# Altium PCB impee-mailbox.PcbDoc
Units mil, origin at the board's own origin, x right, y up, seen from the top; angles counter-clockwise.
Board outline 4040 x 2300 mil, 2 copper layers (Top Layer, Bottom Layer), stack 64.8 mil thick; 81 components, 52 nets, 267 pads, 176 vias.
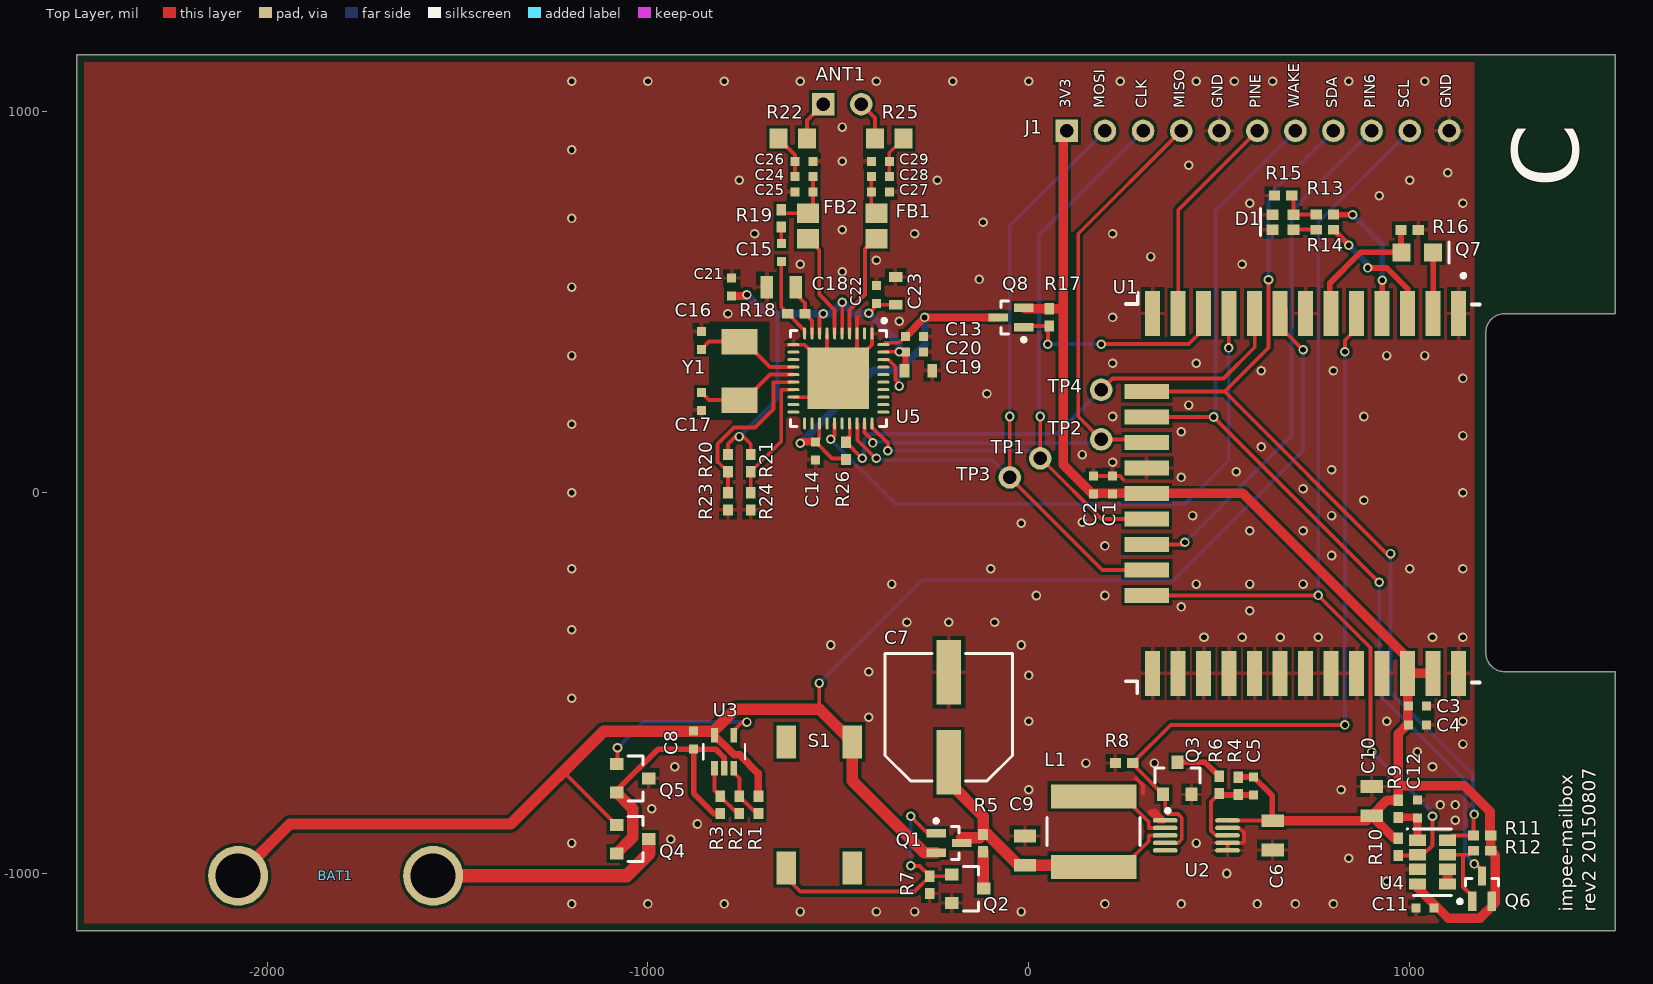
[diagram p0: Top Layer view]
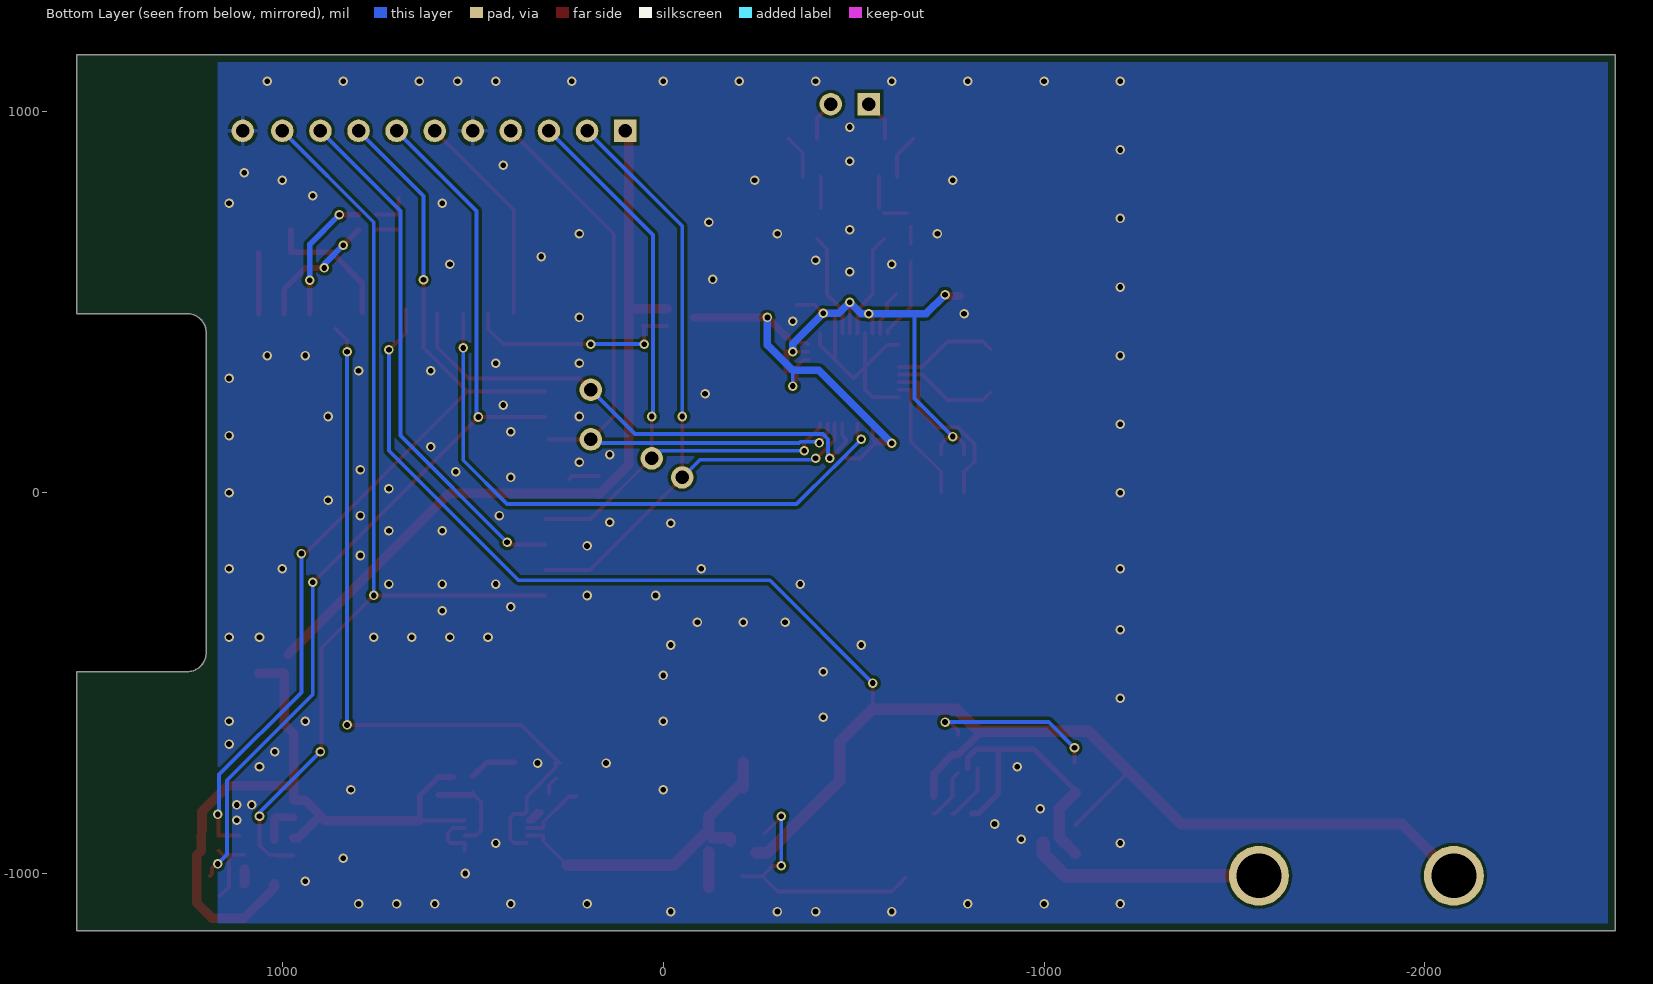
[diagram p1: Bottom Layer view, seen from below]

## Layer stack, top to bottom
Top Solder: solder mask 0.4, Solder Resist, Dk 3.5
Top Layer: signal copper 1.4
Dielectric1: core 62, FR-4, Dk 4.8
Bottom Layer: signal copper 1.4
Bottom Solder: solder mask 0.4, Solder Resist, Dk 3.5

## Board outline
-2500,-1150 -2500,1150 1540,1150 1540,470 1250,470 ccw(c1250,420) 1200,420 1200,-419.9 ccw(c1250,-420) 1250,-470 1540,-470 1540,-1150

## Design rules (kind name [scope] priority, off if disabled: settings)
Clearance "I2C clearance" [(InNet('SCL') AND IsTrack) vs (InNet('SDA') AND IsTrack)] p1: gap=8
Clearance "NPTH Clearance" [IsThruPin and (not PadIsPlated)] p2: gap=10
Clearance "Diff to Poly" [(InDifferentialPairClass('All Differential Pairs')) OR InNet('PinA') OR InNet('PinB') vs InPolygon] p3: gap=30
Clearance "50_OHM to Poly" [InNetClass('50_OHM') and (IsTrack or IsArc) vs InPolygon] p4: gap=30
Clearance "Polygon to All" [InPolygon] p5: gap=8
Clearance [All] p6: gap=6
Clearance "Pad Clearance" [IsPad vs IsPad] p7: gap=8
Clearance "XTAL Clearance" [(InNet('OSC32_IN') OR InNet('OSC32_OUT') OR InComponent('Y1')) vs InPolygon] p8: gap=30
HoleSize [All] p1: absolutevalues=TRUE maxlimit=125 minlimit=1 maxpercent=80.000 minpercent=20.000
HoleToHoleClearance [All] p1: gap=6 allowstackedmicrovias=TRUE
MinimumSolderMaskSliver [All] p1: minsoldermaskwidth=1
PolygonConnect "Direct GND" [InNet('GND') and IsVia] p1: connectstyle=Direct reliefconductorwidth=10 reliefentries=4 polygonreliefangle="90 Angle" airgapwidth=10
PolygonConnect [All] p2: connectstyle=Relief reliefconductorwidth=10 reliefentries=4 polygonreliefangle="90 Angle" airgapwidth=10
RoutingVias [All] p1: holewidth=15 width=25 viastyle="Through Hole" minholewidth=15 minwidth=25 maxholewidth=15 maxwidth=25
SilkToSilkClearance [All] p1: silktosilkclearance=3.94
SilkToSolderMaskClearance [IsPad vs Not HasFootprint('IMP_MODULE')] p1: minsilkscreentomaskgap=7.87 clearancetoexposedcopper=TRUE
SolderMaskExpansion [All] p1: expansion=4
Width 50_OHM [InNetClass('50_OHM')] p1: maxlimit=8.96 minlimit=8.96 preferedwidth=8.96 impedancedriven=TRUE minimp=50.000000 maximp=50.000000 favimp=50.000000
Width [All] p2: maxlimit=100 minlimit=6 preferedwidth=10 minimp=50.000000 maximp=50.000000 favimp=50.000000 checkconnectedcopper=TRUE
25 further rules are at their usual default settings.

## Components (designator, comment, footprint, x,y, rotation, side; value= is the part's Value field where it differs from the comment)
ANT1 "Header" HDR254P1X2-N -540,1020 r0 top
BAT1 "BATTERY" 12BH321P-GR -1820,0 r270 top locked
C1 "Ceramic Capacitor" CAPC1005X07N 220,20 r270 top
C2 "Ceramic Capacitor" CAPC1005X07N 170,20 r270 top
C3 "Ceramic Capacitor" CAPC1005X07N 1020,-560 r180 top
C4 "Ceramic Capacitor" CAPC1005X07N 1020,-610 r180 top
C5 "Ceramic Capacitor" CAPC1005X07N 590,-770 r90 top
C6 "Ceramic Capacitor" CAPC2012X14N 640,-900 r90 top
C7 "Polarized Capacitor" CAPAE8983X55N -210,-590 r90 top
C8 "Ceramic Capacitor" CAPC1005X07N -880,-650 r90 top
C9 "Ceramic Capacitor" CAPC2012X14N -10,-940 r270 top
C10 "Ceramic Capacitor" CAPC2012X14N 900,-810 r270 top
C11 "Ceramic Capacitor" CAPC1005X07N 1040,-1090 r0 top
C12 "Ceramic Capacitor" CAPC1005X07N 1020,-830 r270 top
C13 "Ceramic Capacitor" CAPC1005X07N -300,410 r180 top
C14 "Ceramic Capacitor" CAPC1005X07N -560,110 r90 top
C15 "Ceramic Capacitor" CAPC1005X07N -650,630 r90 top
C16 "Ceramic Capacitor" CAPC1005X07N -860,400 r270 top
C17 "Ceramic Capacitor" CAPC1005X07N -860,240 r90 top
C18 "Ceramic Capacitor" CAPC2012X14N -650,540 r0 top
C19 "Ceramic Capacitor" CAPC1608X10N -290,320 r180 top
C20 "Ceramic Capacitor" CAPC1005X07N -300,370 r180 top
C21 "Ceramic Capacitor" CAPC1005X07N -780,540 r270 top
C22 "Ceramic Capacitor" CAPC1005X07N -400,520 r270 top
C23 "Ceramic Capacitor" CAPC1608X10N -350,530 r270 top
C24 "Ceramic Capacitor" CAPC1005X07N -590,830 r180 top
C25 "Ceramic Capacitor" CAPC1005X07N -590,790 r0 top
C26 "Ceramic Capacitor" CAPC1005X07N -590,870 r180 top
C27 "Ceramic Capacitor" CAPC1005X07N -390,790 r0 top
C28 "Ceramic Capacitor" CAPC1005X07N -390,830 r0 top
C29 "Ceramic Capacitor" CAPC1005X07N -390,870 r180 top
D1 "LED Red and Green" LED1616X07N-REDGREEN 667.56,710.31 r0 top
FB1 "Ferrite Bead" INDC2012X11N -400,700 r90 top
FB2 "Ferrite Bead" INDC2012X11N -580,700 r90 top
J1 "Header" HDR254P1X11-N 100,950 r0 top
L1 "Inductor" INDP6060X28N 170,-890 r90 top
Q1 "PFET" SOT65P210X110-3N -210,-920 r0 top
Q2 "N-Channel MOSFET" SOT95P300X130-3N -160,-1040 r0 top
Q3 "N-Channel MOSFET" SOT95P300X130-3N 390,-750 r90 top
Q4 "N-Channel MOSFET" SOT95P300X130-3N -1040,-910 r0 top
Q5 "N-Channel MOSFET" SOT95P300X130-3N -1040,-750 r0 top
Q6 "PFET" SOT65P210X110-3N 1190,-1040 r90 top
Q7 "PHOTOTRANSISTOR" PHOTOTRANS2012X13 1020,630 r180 top
Q8 "PFET" SOT65P210X110-3N -46.54,460 r180 top
R1 "Resistor" RESC1005X04N -710,-820 r270 top
R2 "Resistor" RESC1005X04N -760,-820 r270 top
R3 "Resistor" RESC1005X04N -810,-820 r270 top
R4 "Resistor" RESC1005X04N 550,-770 r270 top
R5 "Resistor" RESC1005X04N -120,-920 r270 top
R6 "Resistor" RESC1005X04N 500,-767.36 r90 top
R7 "Resistor" RESC1005X04N -260,-1030 r270 top
R8 "Resistor" RESC1005X04N 250,-710 r180 top
R9 "Resistor" RESC1005X04N 970,-830 r90 top
R10 "Resistor" RESC1005X04N 970,-930 r270 top
R11 "Resistor" RESC1005X04N 1190,-900 r180 top
R12 "Resistor" RESC1005X04N 1190,-940 r180 top
R13 "Resistor" RESC1005X04N 777.56,730.31 r180 top
R14 "Resistor" RESC1005X04N 777.56,690.31 r180 top
R15 "Resistor" RESC1005X04N 667.56,780.31 r0 top
R16 "Resistor" RESC1005X04N 1000,690 r0 top
R17 "Resistor" RESC1005X04N 53.46,460 r270 top
R18 "Resistor" RESC1005X04N -610,470 r0 top
R19 "Resistor" RESC1005X04N -650,720 r90 top
R20 "Resistor" RESC1005X04N -790,77.36 r270 top
R21 "Resistor" RESC1005X04N -730,77.36 r270 top
R22 "Resistor" RESC2012X07N -620,930 r0 top
R23 "Resistor" RESC1005X04N -790,-22.64 r270 top
R24 "Resistor" RESC1005X04N -730,-22.64 r270 top
R25 "Resistor" RESC2012X07N -366.38,930 r180 top
R26 "Resistor" RESC1005X04N -480,110 r90 top
S1 "Push Button" BTN600X600X430-4N -550,-820 r0 top
TP1 "Testpoint" TP254P1X1-TH 30,90 r0 top
TP2 "Testpoint" TP254P1X1-TH 190,140 r90 top
TP3 "Testpoint" TP254P1X1-TH -50,40 r90 top
TP4 "Testpoint" TP254P1X1-TH 190,270 r90 top
U1 "imp module" IMP_MODULE 290,490 r270 top locked
U2 "XC9128" MSOP50P490X116-10N 440,-900 r0 top
U3 "MIC841" SOT65P200X125-5N -800,-680 r90 top
U4 "TMD2772" SON97P240X155-8N 1060,-970 r0 top
U5 "PN532" QFN50P600X600X100_HS-41N -500,300 r270 top
Y1 "XTAL" XTAL5032X135 -760,320 r270 top

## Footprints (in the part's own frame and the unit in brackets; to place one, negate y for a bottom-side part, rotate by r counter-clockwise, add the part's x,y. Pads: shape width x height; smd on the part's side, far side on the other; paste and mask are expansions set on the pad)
12BH321P-GR [mm] "2xAA Series Battery Clip with Through-Hole PCB Mount"
  round 4 hole 3: +(25.55,-6.5) -(25.55,6.5)
  body extent -28.45,-16.51 28.45,16.51, height 16.11
BTN600X600X430-4N [mm] "Push Button 4-Terminal"
  rect 1.3x2.2 smd: 1(-2.2,4.2) 2(-2.2,-4.2) 3(2.2,-4.2) 4(2.2,4.2)
  body extent -3,-5 3,5, height 5.07
CAPAE8983X55N [mm] "Aluminum Electrolytic Capacitor, Body 8.30x8.30x5.50mm, IPC Medium Density"
  rect 4.3x1.65 smd: 1(-3,0) 2(3,0)
  silkscreen extent -4.25,-4.25 4.25,4.25, body extent -4.45,-4.15 4.45,4.15, height 6.2
CAPC1005X07N [mm] "Chip Capacitor, 2-Leads, Body 1.0x0.5mm, IPC Medium Density"
  rect 0.6x0.6 smd: 1(-0.6,0) 2(0.6,0)
  body extent -0.5,-0.25 0.5,0.25, height 0.6
CAPC1608X10N [mm] "Chip Capacitor, 2-Leads, Body 1.6x0.8mm, IPC Medium Density"
  rect 0.65x0.9 smd: 1(-0.925,0) 2(0.925,0)
  body extent -0.8,-0.4 0.8,0.4, height 0.95
CAPC2012X14N [mm] "Chip Capacitor, 2-Leads, Body 2.0x1.3mm, IPC Medium Density"
  rect 0.85x1.5 smd: 1(-0.975,0) 2(0.975,0)
  body extent -1,-0.6 1,0.6, height 1.4
HDR254P1X2-N [mm] "HDR, 2.54mm Pitch, 2-Pin"
  rect 1.5x1.5 hole 0.9: 1(0,0)
  round 1.5 hole 0.9: 2(2.54,0)
  body extent -1.27,-1.27 3.81,1.27, height 8.54
HDR254P1X11-N [mm] "HDR, 2.54mm Pitch, 11-Pin"
  rect 1.5x1.5 hole 0.9: 1(0,0)
  round 1.5 hole 0.9: 2(2.54,0) 3(5.08,0) 4(7.62,0) 5(10.16,0) 6(12.7,0) 7(15.24,0) 8(17.78,0) 9(20.32,0) 10(22.86,0) 11(25.5,0)
  body extent -1.27,-1.28 26.85,1.28, height 8.54
IMP_MODULE [mm] "Imp Module, Shadow and Chase"
  rect 3x1 smd: 1(0.5,21.3) 2(0.5,19.6) 3(0.5,17.9) 4(0.5,16.2) 5(0.5,14.5) 6(0.5,12.8) 7(0.5,11.1) 8(0.5,9.4) 9(0.5,7.7) 10(0.5,6) 11(0.5,4.3) 12(0.5,2.6) 13(0.5,0.9) 23(24.5,0.9) 24(24.5,2.6) 25(24.5,4.3) 26(24.5,6) 27(24.5,7.7) 28(24.5,9.4) 29(24.5,11.1) 30(24.5,12.8) 31(24.5,14.5) 32(24.5,16.2) 33(24.5,17.9) 34(24.5,19.6) 35(24.5,21.3)
  rect 1x3 smd: 14(5.7,0.5) 15(7.4,0.5) 16(9.1,0.5) 17(10.8,0.5) 18(12.5,0.5) 19(14.2,0.5) 20(15.9,0.5) 21(17.6,0.5) 22(19.3,0.5)
  silkscreen extent -2.15,-0.89 25.81,22.7, body extent 0,0 25,31, height 1.7
INDC2012X11N [mm] "Chip Inductor, 2-Leads, Body 2.0x1.3mm, IPC Medium Density"
  rect 1.3x1.45 smd: 1(-0.85,0) 2(0.85,0)
  body extent -1.1,-0.72 1.1,0.72, height 1.1
INDP6060X28N [mm] "Precision Wire Wound Inductor, 2-Leads, Body 6.0x6.0mm, IPC Medium Density"
  rect 1.6x5.7 smd: 1(-2.35,0) 2(2.35,0)
  silkscreen extent -0.92,-3.1 0.92,3.1, body extent -3.1,-3.1 3.1,3.1, height 2.8
LED1616X07N-REDGREEN [mm] "Bi-Color LED, 0606 (1616 metric), Red, Green"
  rect 0.8x0.7 smd: AG(0.7,-0.5) AR(0.7,0.5) KG(-0.7,-0.5) KR(-0.7,0.5)
  silkscreen extent -1.5,-0.9 -1.5,0.9, body extent -0.8,-0.8 0.8,0.8, height 0.7
MSOP50P490X116-10N [mm] "MSOP, 10-Leads, Body 3.1x3.1mm (max), Pitch 0.50mm, IPC Medium Density"
  oval 1.65x0.3 smd: 1(-2.075,1) 2(-2.075,0.5) 3(-2.075,0) 4(-2.075,-0.5) 5(-2.075,-1) 6(2.075,-1) 7(2.075,-0.5) 8(2.075,0) 9(2.075,0.5) 10(2.075,1)
  silkscreen extent -2.03,1.53 -1.78,1.78, body extent -1.55,-1.55 1.55,1.55, height 1.16
PHOTOTRANS2012X13 [mm] "Phototransistor, Top View, 0805 (2012 Metric)"
  rect 1.2x1.2 smd: C(-1.05,0) E(1.05,0)
  silkscreen extent -2.1,-0.7 -2.1,0.7, body extent -1,-0.63 1,0.63, height 1.3
QFN50P600X600X100_HS-41N [mm] "QFN, 40-Leads, Body 6.00x6.00mm, Pitch 0.50mm, Thermal Pad 4.10x4.10mm, IPC Medium Density"
  oval 0.8x0.2 smd: 1(-3,2.25) 2(-3,1.75) 3(-3,1.25) 4(-3,0.75) 5(-3,0.25) 6(-3,-0.25) 7(-3,-0.75) 8(-3,-1.25) 9(-3,-1.75) 10(-3,-2.25) 21(3,-2.25) 22(3,-1.75) 23(3,-1.25) 24(3,-0.75) 25(3,-0.25) 26(3,0.25) 27(3,0.75) 28(3,1.25) 29(3,1.75) 30(3,2.25)
  oval 0.2x0.8 smd: 11(-2.25,-3) 12(-1.75,-3) 13(-1.25,-3) 14(-0.75,-3) 15(-0.25,-3) 16(0.25,-3) 17(0.75,-3) 18(1.25,-3) 19(1.75,-3) 20(2.25,-3) 31(2.25,3) 32(1.75,3) 33(1.25,3) 34(0.75,3) 35(0.25,3) 36(-0.25,3) 37(-0.75,3) 38(-1.25,3) 39(-1.75,3) 40(-2.25,3)
  rect 4.1x4.1 smd: 41(0,0)
  silkscreen extent -3.97,-3.2 3.2,3.2, body extent -3.05,-3.05 3.05,3.05, height 1
RESC1005X04N [mm] "Chip Resistor, 2-Leads, Body 1.0x0.5mm, IPC Medium Density"
  rect 0.75x0.65 smd: 1(-0.575,0) 2(0.575,0)
  body extent -0.5,-0.25 0.5,0.25, height 0.35
RESC2012X07N [mm] "Chip Resistor, 2-Leads, Body 2.0x1.3mm, IPC Medium Density"
  rect 1.2x1.35 smd: 1(-0.95,0) 2(0.95,0)
  body extent -1.1,-0.67 1.1,0.67, height 0.7
SON97P240X155-8N [mm] "SON, 8-Leads, Body 3.94x2.36mm, Pitch 0.97mm, IPC Medium Density"
  rect 1.15x0.75 smd mask+0.02: 1(-1,1.455) 2(-1,0.485) 3(-1,-0.485) 4(-1,-1.455) 5(1,-1.455) 6(1,-0.485) 7(1,0.485) 8(1,1.455)
  silkscreen extent -1.73,-2.22 1.28,2.27, body extent -1.28,-2.07 1.28,2.07, height 1.75
SOT65P200X125-5N [mm] "SOT-323-5, SC70-5"
  rect 0.95x0.45 smd paste+0 mask+0.05: 1(-1.1,0.65) 2(-1.1,0) 3(-1.1,-0.65) 4(1.1,-0.65) 5(1.1,0.65)
  silkscreen extent -0.5,-1.4 0.5,1.4, body extent -1.15,-1.05 1.15,1.05, height 1
SOT65P210X110-3N [mm] "SOT23, 3-Leads, Body 2.00x2.10mm, Pitch 0.65mm, IPC Medium Density"
  rect 1.3x0.55 smd: 1(-0.85,0.65) 2(-0.85,-0.65) 3(0.85,0)
  silkscreen extent -0.97,-1.1 0.67,1.6, body extent -0.67,-1.1 0.67,1.1, height 1.1
SOT95P300X130-3N [mm] "SOT-23"
  rect 0.9x0.8 smd: 1(-1.075,0.95) 2(-1.075,-0.95) 3(1.075,0)
  silkscreen extent -0.3,-1.5 0.7,1.5, body extent -1.17,-1.45 1.17,1.47, height 1
TP254P1X1-TH [mm] "Testpoint, Through Hole, 2.54mm Pitch, 1-Pin"
  round 1.5 hole 0.9 mask+0.102: 1(0,0)
XTAL5032X135 [mm] "XTAL5032X135 xtal"
  rect 1.7x2.4 smd: 1(-1.95,0) 2(1.95,0)
  body extent -3.05,-1.75 3.05,1.75, height 1.44

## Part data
ANT1: library part HDR00002, "HDR, 1x2 Pin, 2.54mm Pitch, Gold Flash, Vertical, TH"
BAT1: library part BAT00006, "2xAA Series Battery Clip with Through-Hole PCB Mount"
C1 C3 C26 C29: library part CAPC00043, "CAP,C0G,100pF,5%,50V,0402"
C2 C4 C8 C11 C12 C13 C14: library part CAPC00005, "CAP,X5R,1.0uF,10%,6.3V, 0402,#"
C5: library part CAPC00041, "CAP,C0G,12pF,5%,50V,0402#"
C6: library part CAPC00039, "CAP,X5R,22uF,10%,6.3V,0805,#"
C7: library part CAPC00106, "CAP,Alum,330uF,20%,6.3V,SMD"
C9 C10: library part CAPC00036, "CAP,X5R,10uF,10%,6.3V,0805,#"
C15: library part CAPC00092, "CAP,X7R,1000pF,10%,50V,0402"
C16 C17: library part CAPC00044, "CAP,C0G,27pF,5%,50V,0402"
C18: library part CAPC00023, "CAP,X7R,0.1uF,10%,50V,0805"
C19 C23: library part CAPC00033, "CAP,X5R,4.7uF,10%,6.3V,0603,#"
C20 C21 C22: library part CAPC00002, "CAP,X5R,0.1uF,10%,6.3V, 0402,#"
C24 C28: library part CAPC00045, "CAP,C0G,56pF,5%,50V,0402"
C25 C27: library part CAPC00110, "CAP,C0G,220pF,25%,50V,0402"
D1: library part LED00012, "LED, Red and Green, 2/2V, 631/571nm, 25/35mcd, SMT"
FB1 FB2: library part FB00008, "FERR BD, 25 Ohm @ 25Mhz, 150mA, 550 mOhm, 0805"
J1: library part HDR00036, "HDR, 1x11 Pin, 2.54mm Pitch, Gold Flash, Vertical, TH"
L1: library part IND00007, "IND, 4.7uH, 20%, 2.7A Isat, 403 mOhm, 6028"
Q1 Q6 Q8: library part PFET00009, "PFET, 20V, 820mA, 1V, SOT323"
Q2 Q4 Q5: library part NFET00004, "NFET, 20V, 4.2A, SOT23"
Q3: library part NFET00003, "NFET, 25V, 220mA, SOT23"
Q7: library part PHOTO00002, "Phototrans, Clear, Top View, 940nm, 0.4V, 1mA, 0805"
R1: library part RES00009, "RES,470K,5%,0.063W,0402"
R2 R5: library part RES00008, "RES,47K,5%,0.063W,0402"
R3: library part RES00054, "RES,560K,1%,0.063W,0402"
R4: library part RES00015, "RES,270K,5%,0.063W,0402"
R6: library part RES00041, "RES,43K,1%,0.063W,0402"
R7 R8 R12 R17 R20 R21 R23 R24: library part RES00001, "RES,100K,5%,0.063W,0402,#"
R9: library part RES00060, "RES,22 Ohm,5%,0.063W,0402"
R10 R11 R26: library part RES00005, "RES,4.7K,5%,0.063W,0402,#"
R13 R14: library part RES00024, "RES,100,1%,0.063W,0402,#"
R15: library part RES00006, "RES,10k,5%,0.063W,0402,#"
R16: library part RES00007, "RES,22K,5%,0.063W,0402"
R18: library part RES00003, "RES,1K,5%,0.063W,0402,#"
R19: library part RES00100, "RES,1.5K Ohm,1%,0.063W,0402"
R22 R25: library part RES00018, "RES,1 Ohm,1%,0.25W,0805"
S1: library part BTN00001, "SPST- NO Momentary Button, 160g Force, SMD"
TP1 TP2 TP3 TP4: library part ELEC00022
U1: library part MOD00002, "Module, Electric Imp Solder Down with Antenna"
U2: library part IC00026, "IC, DC/DC boost,Adjustable, 6 VIN, 500mA, MSOP10"
U3: library part IC00032, "IC, Comparator with Reference and Programmable Hysteresis, SOT-353"
U4: library part IC00196, "IC, Sensor, ALS and Proximity, I2C"
U5: library part IC00195, "IC, NFC Reader, QFN40"
Y1: library part XTAL00003, "XTAL, 27.12MHz, 30ppm, 18pF, 50 Ohm, 5032"

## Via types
v1: diameter 25, hole 15, Top Layer to Bottom Layer, tented both sides, 172 vias
v2: diameter 25, hole 15, Top Layer to Bottom Layer, 4 vias

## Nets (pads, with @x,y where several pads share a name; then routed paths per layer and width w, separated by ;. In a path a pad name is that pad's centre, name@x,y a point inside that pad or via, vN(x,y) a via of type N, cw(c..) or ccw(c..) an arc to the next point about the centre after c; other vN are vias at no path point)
BAT+: BAT1.+ C8.2 Q1.2 Q4.1 R1.1 S1.4 U1.8 U3.5 | length 4636.3
  Top Layer w10: -1220,-734.92 Q4.1 ; -550,-568.03 v1(-550,-500) ; U1.8@676,481.55 676,419 v2(720,375)
  Top Layer w20: -835.91,-626.38 U3.5 -773.68,-688.61 -758.92,-688.61 -710,-737.53 R1.1
  Top Layer w30: BAT1.+ -1940,-870 -1360,-870 -1116.38,-626.38 C8.2 -835.91,-626.38 -827.59,-626.38 -770,-568.78 -549.25,-568.78 S1.4 -463.39,-756.61 -274.41,-945.59 Q1.2
  Bottom Layer w10: v1(-550,-500) -280,-230 380,-230 720,110 v2(720,375)
DVDD: C19.2 C20.2 C21.2 C22.2 C23.2 R20.1 R21.1 U5.5 U5.8 U5.39 | length 1362.9
  Top Layer w10: R20.1 -790,127.36 -770,147.36 v1(-760,147.36) -750,147.36 -730,127.36 R21.1 ; U5.8 -549.21,460.79 v1(-540,470) ; U5.5@-490,418.27 v1(-490,500) ; v1(-420,470.79) -397.2,493.58 C23.2 ; U5.39@-380.79,370 C20.2
  Top Layer w15: C19.2 -323.62,320 C20.2
  Top Layer w20: C21.2 -743.62,516.38 v1(-740,520)
  Bottom Layer w10: v1(-760,147.36) -660,247.36 -660,470
  Bottom Layer w20: v1(-740,520) -690,470 -660,470 v1(-540,470) -520,470 v1(-490,500) -460.79,470.79 v1(-420,470.79) -340,390.79 v1(-340,370)
GND: C1.1 C2.1 C3.1 C4.1 C6.1 C7.2 C9.1 C10.1 C11.1 C12.1 C13.1 C14.1 C16.1 C17.1 C18.1 C19.1 C20.1 C21.1 C22.1 C23.1 C25.1 C26.1 C27.2 C29.2 D1.KG D1.KR J1.5 J1.11 Q2.2 Q3.2 Q5.3 R7.2 R8.2 R15.1 R16.2 R23.2 R24.2 U1.1 U1.7 U1.13 U1.17 U1.23 U1.24 U1.25 U1.26 U1.27 U1.28 U1.29 U1.30 U1.31 U1.32 U1.35 U2.1 U2.6 U2.7 U2.9 U4.3 U5.1 U5.3 U5.7 U5.11 U5.18 U5.41 | length 1008.1
  Top Layer w10: U5.18 -549.21,250.79 -529.53,270.47 U5.41@-529.53,329.53 ; U5.11 -588.58,388.58 U5.41@-529.53,329.53 ; U5.7 U5.41@-529.53,329.53 ; -450.79,459.21 U5.3 U5.41@-450.79,349.21 ; U5.1 -411.42,388.58 U5.41@-450.79,349.21 ; C2.1 C1.1 239.1,43.62 247.6,35.12 ; 280,-750 281.78,-750 300,-768.22 300,-790 ; U2.6 U2.7 560.66,-919.68 565.17,-915.17 565.17,-893 552.49,-880.31 U2.9 ; U5.41@-529.53,329.53 U5.41 U5.41@-450.79,349.21
  Top Layer w15: 320,-840 340.91,-860.91 354.49,-860.91 330,-836.42
  other v1: -600,-1100 -400,-1100 -300,-1100 -20,-1100 -1200,-1080 -1000,-1080 -800,-1080 200,-1080 400,-1080 600,-1080 700,-1080 800,-1080 940,-1020 520,-1000 840,-960 -1200,-920 440,-920 -940,-910 -870,-870 1120,-860 -990,-830 1080,-820 1120,-820 0,-780 820,-780 -930,-720 1060,-720 150,-710 330,-710 1020,-680 1140,-660 0,-600 940,-600 1140,-600 -420,-590 -1200,-540 0,-480 -420,-470 -520,-400 -20,-400 460,-380 560,-380 660,-380 760,-380 1060,-380 1140,-380 -1200,-360 -320,-340 -210,-340 -90,-340 580,-310 400,-300 20,-270 200,-270 -360,-240 440,-240 580,-240 720,-240 -1200,-200 -100,-200 1000,-200 1140,-200 795,-165 200,-140 580,-100 720,-100 -20,-80 140,-77.31 430,-60 795,-60 880,-20 -1200,0 1140,0 720,10 400,40 545,55 795,60 220,80 140,100 610,120 1140,150 400,160 -1200,180 220,200 880,200 420,230 -110,260 1140,300 610,320 800,320 220,340 440,340 -1200,360 940,360 1040,360 -340,450 220,460 -790,470 -1200,540 -130,560 -490,580 -600,600 560,600 -400,610 320,620 -720,680 -300,680 220,680 -490,690 -120,710 -1200,720 580,760 1140,760 920,780 -760,820 -240,820 1000,820 1100,840 420,860 -490,870 -1200,900 -490,960 -1200,1080 -1000,1080 -800,1080 -600,1080 -400,1080 -200,1080 0,1080 240,1080 440,1080 540,1080 640,1080 840,1080 1040,1080
I2C_SCL: J1.10 R10.2 U1.22 U4.2 | length 2648.7
  Top Layer w10: U1.22 v1(759.84,-269.84) 897.11,-407.11 897.11,-677.11 v1(900,-680) ; R10.2 U4.2@1018.9,-952.64 ; U4.2 1035.4,-950.91 1060,-926.3 v1(1060,-850)
  Bottom Layer w10: v1(759.84,-269.84) 759.84,709.84 J1.10 ; v1(900,-680) 1060,-840 v1(1060,-850)
I2C_SDA: J1.8 R11.2 U1.14 U4.8 | length 2520.9
  Top Layer w10: U1.14 514.41,265.59 ; v1(629.39,559.39) 629.39,380.57 514.41,265.59 ; v1(950,-160) 950,-170 514.41,265.59 ; U4.8@1112.09,-900 R11.2 1167.36,-847.64 v1(1170,-845)
  Bottom Layer w10: v1(629.39,559.39) 629.39,779.39 J1.8 ; v1(950,-160) 950,-524.43 1166,-740.43 1166,-841 v1(1170,-845)
IMP_WAKEUP: J1.7 Q6.3 U1.15 | length 2516.2
  Top Layer w10: U1.15 v1(485.06,198.66) v2@919.36,-235.64 ; v2(1170,-975) 1175,-975 1185,-985 1185,-1001.54 Q6.3
  Bottom Layer w10: v1(485.06,198.66) 490,203.6 490,740 J1.7 ; v2(920,-235) 920,-530 1145,-755 1145,-950 v2(1170,-975)
LED_GREEN: R14.1 U1.3 | length 319.7
  Top Layer w15: R14.1@800,690.12 840,650.12 v1(840,650) ; v1(890,590) 940,590 994.72,535.28 U1.3
  Bottom Layer w15: v1(840,650) v1@890,600
LED_RED: R13.1 U1.4 | length 341.4
  Top Layer w15: R13.1@800.51,730 v1(850,730) ; U1.4 v1(927.8,557.8)
  Bottom Layer w15: v1(850,730) 927.8,652.2 v1(927.8,557.8)
NetANT1_1: ANT1.1 R22.2 | length 107.6
  Top Layer w10: R22.2 -582.6,977.4 ANT1.1
NetANT1_2: ANT1.2 R25.2 | length 105
  Top Layer w10: ANT1.2 -403.78,983.78 R25.2
NetBAT1_-: BAT1.- Q4.3 | length 618.2
  Top Layer w35: BAT1.- -1055.91,-1005.91 -997.68,-947.68 Q4.3@-997.68,-920
NetC5_1: C5.1 R4.2 R6.1 U2.8 | length 245.3
  Top Layer w10: 478.21,-811.79 478.21,-887.32 490.9,-900 U2.8 ; 479.11,-810.89 R6.1
  Top Layer w15: R6.1 503.62,-793.62 C5.1
NetC7_1: C7.1 C9.2 L1.1 Q1.3 R5.1 U2.3 | length 863.5
  Top Layer w10: L1.1@251.61,-978.39 314.83,-915.17 314.83,-900 U2.3
  Top Layer w30: C7.1@-210,-774.96 C7.1@-210,-760 ; C7.1 C7.1@-210,-760 ; Q1.3@-176.54,-915 -176.54,-906.64 -129.28,-906.64 R5.1 ; L1.1@251.61,-978.39 C9.2 -26.99,-978.39 -108.02,-897.36 R5.1 ; C7.1@-210,-760 -120,-850 R5.1
NetC8_1: C8.1 Q4.2 Q5.2 R3.2 U3.2 | length 767.4
  Top Layer w15: Q5.2@-1082.32,-782.09 -973.86,-673.62 C8.1 ; R3.2 -827.36,-842.64 -880,-790 C8.1 ; U3.2 -800,-695.52 -821.9,-673.62 C8.1
  Top Layer w30: Q4.2 -1040,-905.08 -1040,-829.72 Q5.2
NetC12_2: C12.2 R9.1 U4.1 | length 109.8
  Top Layer w20: R9.1 1019.02,-852.64 C12.2 1020.63,-854.25 U4.1
NetC15_2: C15.2 R19.1 | length 43.7
  Top Layer w10: C15.2 R19.1
NetC16_2: C16.2 U5.14 Y1.1 | length 277.5
  Top Layer w10: C16.2 -839.61,396.77 Y1.1 -746.77,396.77 -680,330 U5.14@-618.58,330
NetC17_2: C17.2 U5.15 Y1.2 | length 277.8
  Top Layer w10: C17.2 -839.61,243.23 Y1.2 -746.77,243.23 -680,310 U5.15@-618.27,310
NetC24_1: C24.1 C25.2 FB2.2 R19.2 | length 143.7
  Top Layer w10: R19.2@-640.83,733.46 FB2.2 ; FB2.2@-566.38,747.09 C25.2 C24.1
NetC24_2: C24.2 C26.2 R22.1 | length 118.1
  Top Layer w10: R22.1 -613.62,886.22 C26.2 C24.2
NetC27_1: C27.1 C28.1 FB1.2 | length 82.9
  Top Layer w10: FB1.2@-413.62,747.09 C27.1 C28.1
NetC28_2: C28.2 C29.1 R25.1 | length 115.5
  Top Layer w10: C28.2 C29.1 -366.38,892.6 R25.1
NetD1_AG: D1.AG R14.2 | length 59.5
  Top Layer w10: D1.AG R14.2@754.61,690.63
NetD1_AR: D1.AR R13.2 R15.2 | length 104.9
  Top Layer w10: R15.2@695.12,775.39 D1.AR R13.2@754.61,730
NetL1_2: L1.2 U2.2 | length 174.2
  Top Layer w10: L1.2@227.48,-797.48 247.48,-797.48 314.83,-864.83 314.83,-880.31 U2.2
NetQ1_1: Q1.1 Q2.1 R7.1 S1.2 | length 715.4
  Top Layer w10: S1.2@-636.61,-1010.75 -600,-1047.36 -300,-1047.36 R7.1 ; v1(-310,-980) -287.36,-980 R7.1 ; v1(-310,-850) Q1.1@-265.59,-894.41 ; Q2.1@-207.09,-1007.36 R7.1
  Bottom Layer w10: v1(-310,-980) v1(-310,-850)
NetQ2_3: Q2.3 R5.2 | length 95
  Top Layer w30: Q2.3@-120,-1037.68 R5.2
NetQ3_3: Q3.3 R6.2 | length 125.3
  Top Layer w15: Q3.3 462.95,-707.68 R6.2
NetQ5_1: Q5.1 U3.4 | length 451.9
  Top Layer w10: Q5.1@-1080,-710.28 v1(-1080,-670) ; U3.4 -774.41,-624.41 v1@-752.28,-602.28
  Bottom Layer w10: v1(-1080,-670) -1012.28,-602.28 v1(-740,-602.28)
NetQ6_1: Q6.1 R12.2 U4.7 | length 191.1
  Top Layer w10: U4.7 1140,-950.91 ; Q6.1@1164.41,-1059.41 1140,-1035 1140,-950.91 ; R12.2 1156.46,-950.91 1140,-950.91
NetR1_2: R1.2 R2.1 U3.3 | length 136.5
  Top Layer w10: U3.3@-774.41,-735.59 -760,-750 R2.1 -714.72,-842.64 R1.2
NetR2_2: R2.2 R3.1 U3.1 | length 149.3
  Top Layer w10: U3.1 -825.59,-781.77 R3.1 -764.72,-842.64 R2.2
NetR20_2: R20.2 R23.1 U5.16 | length 445.5
  Top Layer w10: -817.36,80 -817.36,127.36 -773.86,170.86 -719.14,170.86 -670,220 -670,290 -669.84,290.16 U5.16 ; -815.28,80 R20.2 R23.1
NetR21_2: R21.2 R24.1 U5.17 | length 335.2
  Top Layer w10: R24.1 R21.2 -650,134.72 -650,270 -649.53,270.47 U5.17
NetU4_5: U4.5 U4.6 | length 38.2
  Top Layer w25: U4.5 U4.6
OPTO_BIAS: Q7.C U1.2 | length 159.4
  Top Layer w15: U1.2 Q7.C@1061.65,629.69
OPTO_IN: Q7.E R16.1 U1.6 | length 355.5
  Top Layer w15: U1.6@790,474.25 790,550 871.3,631.3 977.36,631.3 R16.1
PIN_6: J1.9 U1.20 | length 1385.8
  Top Layer w10: U1.20 404.02,-135.98 v1(410,-130)
  Bottom Layer w10: v1(410,-130) 690,150 690,740 J1.9
PIN_E: J1.6 U1.12 | length 565.7
  Top Layer w10: U1.12 392.36,742.36 J1.6
PN532_DISABLE: Q8.1 R17.2 U1.11 | length 574.1
  Top Layer w10: Q8.1@-10.12,437.36 R17.2 ; v1(50,390) R17.2@50,433.9 ; v1(190,390) 420,390 459.29,429.29 U1.11
  Bottom Layer w10: v1(50,390) v1(190,390)
PN532_IRQ: U1.10 U5.25 | length 1593.6
  Top Layer w10: v1(-520,140) -509.84,150.16 U5.25 ; v2(525,380) U1.10@525,469.1
  Bottom Layer w10: v1(-520,140) -520,139.4 -447.1,66.5 -446.5,66.5 -350,-30 410,-30 525,85 v2(525,380)
PN532_NCS: R26.2 TP4.1 U1.9 U5.27 | length 1380
  Top Layer w10: U5.27@-470,181.42 -470,150 -480,140 R26.2 v1(-437.36,90) ; TP4.1 220,300 511.3,300 593.15,381.85 U1.9
  Bottom Layer w10: v1(-437.36,90) -432.97,94.39 -432.97,140.26 -419.21,154.03 74.03,154.03 TP4.1
PN532_POWER: C13.2 C14.2 Q8.3 R26.1 U5.23 U5.38 U5.40 | length 1159.2
  Top Layer w10: U5.23@-550,181.1 -550,143.62 C14.2 -516.38,90 R26.1@-482.64,90 ; U5.38 -368.64,349.21 -350.21,330.79 -350.21,297.51 -340,287.3 v1(-340,280) ; U5.40@-380.47,390 -376.97,393.5 -340.12,393.5 C13.2
  Top Layer w20: v1(-600,130) -596.38,133.62 C14.2 ; C13.2 v1(-273.62,460) Q8.3
  Bottom Layer w10: v1(-340,280) -340,321.5
  Bottom Layer w20: v1(-600,130) -408.5,321.5 -340,321.5 -273.62,387.88 v1(-273.62,460)
POWER_EN: Q3.1 R8.1 U1.5 U2.4 | length 1965.9
  Top Layer w10: R8.1 372.64,-610 v1(830,-610) ; R8.1@282.64,-710 282.64,-722.36 Q3.1 358.31,-798.03 358.31,-838.57 363.46,-843.72 391.88,-843.72 401.79,-853.63 401.79,-910 392.1,-919.68 U2.4 ; v1(830,370) 830,400 U1.5@860.87,430.87
  Bottom Layer w10: v1(830,-610) v1(830,370)
RX: C15.1 R18.1 U5.10 | length 213.7
  Top Layer w10: C15.1 -650,487.36 R18.1 -588.58,425.94 U5.10
SPI_MISO: J1.4 TP2.1 U1.16 U5.29 | length 1724.3
  Top Layer w10: U5.29 -431.1,157.87 -409.47,136.24 v1(-409.47,130.53) ; U1.16@301.42,140 TP2.1 130,200 130,680 J1.4
  Bottom Layer w10: v1(-409.47,130.53) -406.5,133.5 -360.27,133.5 -357.29,130.53 180.53,130.53 TP2.1
SPI_MOSI: J1.2 TP3.1 U1.21 U5.28 | length 1961.9
  Top Layer w10: U5.28 -450,181.1 -450,137.82 -400,87.82 v1(-400,90) ; v1(-50,200) TP3.1 192.91,-202.91 U1.21
  Bottom Layer w10: v1(-400,90) -396.5,86.5 -96.5,86.5 TP3.1 ; v1(-50,200) -50,700 J1.2
SPI_SCLK: J1.3 TP1.1 U1.19 U5.30 | length 1801.6
  Top Layer w10: U5.30 -411.42,171.42 -370,130 v1(-370,110) ; TP1.1 v1(30,200) ; TP1.1@41.89,80 190.94,-69.06 U1.19
  Bottom Layer w10: v1(-370,110) 10,110 TP1.1 ; v1(30,200) 26.5,203.5 26.5,676.5 J1.3
TX1: FB1.1 U5.4 | length 276.2
  Top Layer w10: U5.4 -470.47,479.53 -430,520 -430,640 FB1.1@-403.46,666.54
TX2: FB2.1 U5.6 | length 277.5
  Top Layer w10: FB2.1 -550,636.54 -550,520 -509.84,479.84 U5.6
VBAT_3V3: C1.2 C2.2 C3.2 C4.2 C5.2 C6.2 C10.2 C11.2 J1.1 Q6.2 Q8.2 R4.1 R9.2 R10.1 R11.1 R12.1 R17.1 U1.18 U1.33 U1.34 U2.10 U4.4 | length 3972
  Top Layer w10: U2.10 C6.2@639.02,-860.63
  Top Layer w15: R4.1@550.98,-746.38 C5.2 639.02,-795.39 C6.2@639.02,-860.63
  Top Layer w25: Q8.2@-10.12,482.64 R17.1 82.64,482.64 ; J1.1@90,940 90,73.84 167.46,-3.62 C2.2 ; C2.2@171.5,-2.13 U1.18 562.13,-2.13 U1.33@985,-425 ; C6.2 886.77,-861.61 C10.2 ; R10.1 958.98,-907.36 C10.2 ; U4.4@1019.72,-1035.94 1101.34,-1117.56 1185,-1117.56 1185.31,-1117.24 ; U4.4@1019.72,-1026.38 U4.4 U4.4@1024.5,-1031.16 ; U1.34 U1.33 994.72,-608.35 970,-633.07 970,-770 ; 1185,-1116.93 1225,-1076.93 1225,-952.36 R12.1 R11.1 ; R11.1@1211,-887.99 1211,-837.16 1143.84,-770 970,-770 ; C10.2 941.02,-807.36 R9.2 970,-770
VMID: C18.2 R18.2 U5.9 | length 121.2
  Top Layer w10: C18.2@-611.61,521.61 -587.36,497.36 R18.2 -568.9,451.54 U5.9
pads on no net: S1.1 S1.3 U2.5 U5.2 U5.12 U5.13 U5.19 U5.20 U5.21 U5.22 U5.24 U5.26 U5.31 U5.32 U5.33 U5.34 U5.35 U5.36 U5.37

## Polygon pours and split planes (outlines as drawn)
GND on Top Layer "Top Layer-GND" (solid, remove dead copper, pour order 3): -2480,-1130 -2480,1130 1170,1130 1170,-1130
GND on Bottom Layer "Bottom Layer-GND" (solid, remove dead copper, pour order 2): -2480,-1130 -2480,1130 1170,1130 1170,-1130

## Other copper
Top Layer:
  pour cut-out: -840,450 -680,450 -680,190 -840,190

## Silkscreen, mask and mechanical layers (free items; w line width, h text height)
Top Overlay:
  text "3V3" at 120,1010 h50 r90
  text "MOSI" at 210,1010 h50 r90
  text "CLK" at 320,1010 h50 r90
  text "MISO" at 420,1010 h50 r90
  text "GND" at 520,1010 h50 r90
  text "PINE" at 620,1010 h50 r90
  text "WAKE" at 720,1010 h50 r90
  text "SDA" at 820,1010 h50 r90
  text "PIN6" at 920,1010 h50 r90
  text "SCL" at 1010,1010 h50 r90
  text "GND" at 1120,1010 h50 r90
  text "C" at 1500,800 h300 r90
  text "impee-mailbox / rev2 20150807" at 1500,-1100 h60 r90
Mechanical 14:
  lines w10: -2500,-1150 -2500,1150 1540,1150 1540,470 1250,470 ccw(c1250,425) 1205,425 1205,-425 ccw(c1250,-425) 1250,-470 1540,-470 1540,-1150 -2500,-1150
